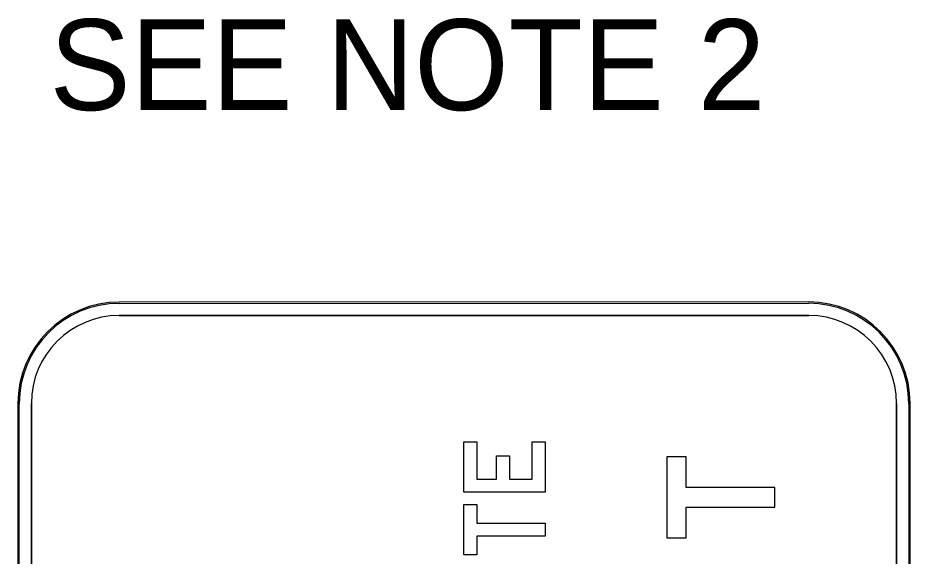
# Model space of a CAD drawing. Extents: x 46672 to 47298, y 5424 to 5829.
# Drawn here: x 47184.94 to 47212.44, y 5719.59 to 5736.17 of the extents above; entities that cross this region are included whole.
import ezdxf

# ---------------------------------------------------------------- set-up
doc = ezdxf.new("R2010")
doc.units = 0
for name, color, linetype in [('GSBWFill', 7, 'Continuous'), ('GSColorFill', 7, 'Continuous'), ('GSOutline', 7, 'Continuous'), ('SignPanel', 7, 'Continuous'), ('TextLabel', 7, 'Continuous')]:
    doc.layers.add(name, color=color, linetype=linetype)

msp = doc.modelspace()

# ---------------------------------------------------------------- linework, layer by layer
at = {"layer": 'GSBWFill'}
for p, q in [((47209.309, 5727.418), (47188.063, 5727.417)), ((47188.063, 5727.001), (47209.31, 5727.002)), ((47184.939, 5724.293), (47184.94, 5690.548)), ((47185.357, 5690.548), (47185.355, 5724.293)), ((47212.018, 5724.294), (47212.019, 5690.554)), ((47212.436, 5690.554), (47212.434, 5724.294))]:
    msp.add_line(p, q, dxfattribs=at)
for centre, radius, start, end in [((47188.063, 5724.293), 3.124, 90.0026, 180.0026), ((47209.31, 5724.294), 3.124, 0.0026, 90.0026), ((47188.063, 5724.293), 2.708, 90.0026, 180.0026), ((47209.31, 5724.294), 2.708, 0.0026, 90.0026)]:
    msp.add_arc(centre, radius, start, end, dxfattribs=at)
at = {"layer": 'GSColorFill'}
for p, q in [((47209.309, 5727.418), (47188.063, 5727.417)), ((47184.939, 5724.293), (47184.94, 5690.548)), ((47212.436, 5690.549), (47212.434, 5724.294))]:
    msp.add_line(p, q, dxfattribs=at)
for centre, start, end in [((47188.063, 5724.293), 90.0026, 180.0026), ((47209.31, 5724.294), 0.0026, 90.0026)]:
    msp.add_arc(centre, 3.124, start, end, dxfattribs=at)
at = {"layer": 'GSOutline'}
for p, q in [((47209.309, 5727.418), (47188.063, 5727.417)), ((47209.31, 5727.002), (47188.063, 5727.001)), ((47184.939, 5724.293), (47184.94, 5690.548)), ((47185.355, 5724.293), (47185.357, 5690.548)), ((47212.019, 5690.549), (47212.018, 5724.294)), ((47212.436, 5690.549), (47212.434, 5724.294))]:
    msp.add_line(p, q, dxfattribs=at)
for centre, radius, start, end in [((47188.063, 5724.293), 3.124, 90.0026, 180.0026), ((47209.31, 5724.294), 3.124, 0.0026, 90.0026), ((47188.063, 5724.293), 2.708, 90.0026, 180.0026), ((47209.31, 5724.294), 2.708, 0.0026, 90.0026)]:
    msp.add_arc(centre, radius, start, end, dxfattribs=at)
at = {"layer": 'SignPanel'}
for p, q in [((47209.309, 5727.418), (47188.063, 5727.417)), ((47209.309, 5727.418), (47188.063, 5727.417)), ((47188.063, 5727.376), (47209.309, 5727.377)), ((47188.063, 5727.001), (47209.31, 5727.002)), ((47184.939, 5724.293), (47184.94, 5690.548)), ((47184.939, 5724.293), (47184.94, 5690.548)), ((47184.982, 5690.548), (47184.98, 5724.293)), ((47185.357, 5690.548), (47185.355, 5724.293)), ((47212.018, 5724.294), (47212.019, 5690.554)), ((47212.392, 5724.294), (47212.394, 5690.55)), ((47212.436, 5690.554), (47212.434, 5724.294)), ((47212.436, 5690.55), (47212.434, 5724.294))]:
    msp.add_line(p, q, dxfattribs=at)
for points in [[(47199.086, 5723.106), (47199.086, 5721.956), (47199.686, 5721.956), (47199.686, 5722.683), (47200.086, 5722.683), (47200.086, 5721.956), (47200.786, 5721.956), (47200.786, 5723.106), (47201.186, 5723.106), (47201.186, 5721.556), (47198.686, 5721.556), (47198.686, 5723.106)], [(47199.086, 5723.106), (47199.086, 5721.956), (47199.686, 5721.956), (47199.686, 5722.683), (47200.086, 5722.683), (47200.086, 5721.956), (47200.786, 5721.956), (47200.786, 5723.106), (47201.186, 5723.106), (47201.186, 5721.556), (47198.686, 5721.556), (47198.686, 5723.106)], [(47199.086, 5723.106), (47199.086, 5721.956), (47199.686, 5721.956), (47199.686, 5722.683), (47200.086, 5722.683), (47200.086, 5721.956), (47200.786, 5721.956), (47200.786, 5723.106), (47201.186, 5723.106), (47201.186, 5721.556), (47198.686, 5721.556), (47198.686, 5723.106)], [(47205.535, 5720.153), (47205.535, 5721.103), (47208.268, 5721.103), (47208.268, 5721.703), (47205.535, 5721.702), (47205.535, 5722.652), (47204.935, 5722.652), (47204.935, 5720.153)], [(47205.535, 5720.153), (47205.535, 5721.103), (47208.268, 5721.103), (47208.268, 5721.703), (47205.535, 5721.702), (47205.535, 5722.652), (47204.935, 5722.652), (47204.935, 5720.153)], [(47205.535, 5720.153), (47205.535, 5721.103), (47208.268, 5721.103), (47208.268, 5721.703), (47205.535, 5721.702), (47205.535, 5722.652), (47204.935, 5722.652), (47204.935, 5720.153)], [(47198.686, 5721.181), (47199.086, 5721.181), (47199.086, 5720.607), (47201.186, 5720.607), (47201.186, 5720.207), (47199.086, 5720.207), (47199.086, 5719.632), (47198.686, 5719.632)], [(47198.686, 5721.181), (47199.086, 5721.181), (47199.086, 5720.607), (47201.186, 5720.607), (47201.186, 5720.207), (47199.086, 5720.207), (47199.086, 5719.632), (47198.686, 5719.632)], [(47198.686, 5721.181), (47199.086, 5721.181), (47199.086, 5720.607), (47201.186, 5720.607), (47201.186, 5720.207), (47199.086, 5720.207), (47199.086, 5719.632), (47198.686, 5719.632)]]:
    msp.add_lwpolyline(points, close=True, dxfattribs=at)
for centre, radius, start, end in [((47188.063, 5724.293), 3.124, 90.0026, 180.0026), ((47188.063, 5724.293), 3.124, 90.0026, 180.0026), ((47188.063, 5724.293), 3.083, 90.0026, 180.0026), ((47209.31, 5724.294), 3.124, 0.0026, 90.0026), ((47209.31, 5724.294), 3.124, 0.0026, 90.0026), ((47209.31, 5724.294), 3.083, 0.0026, 90.0026), ((47188.063, 5724.293), 2.708, 90.0026, 180.0026), ((47209.31, 5724.294), 2.708, 0.0026, 90.0026)]:
    msp.add_arc(centre, radius, start, end, dxfattribs=at)

# ---------------------------------------------------------------- texts
at = {"layer": 'TextLabel'}
msp.add_text('SEE NOTE 2', height=2.8, dxfattribs=at).set_placement((47185.916, 5733.328))

doc.saveas('drawing.dxf')
